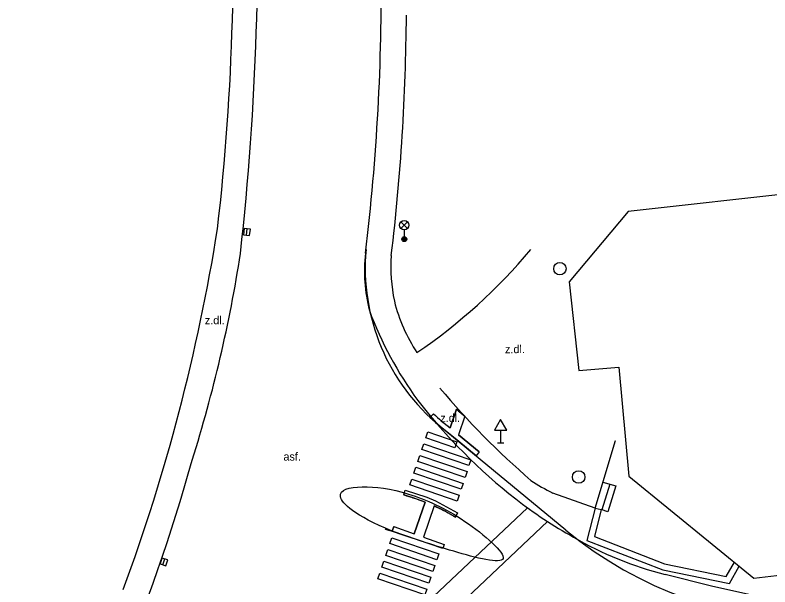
# Model space of a CAD drawing. Extents: x -438303 to -437792, y -1133191 to -1132731.
# Drawn here: x -438175.2 to -438114.5, y -1132946.7 to -1132900.7 of the extents above; entities that cross this region are included whole.
import ezdxf

# ---------------------------------------------------------------- set-up
doc = ezdxf.new("R2010")
doc.units = 0
for name, color, linetype in [('Vrstva 1', 7, 'Continuous'), ('Vrstva 10', 7, 'Continuous'), ('Vrstva 11', 7, 'Continuous'), ('Vrstva 15', 7, 'Continuous'), ('Vrstva 27', 7, 'Continuous'), ('Vrstva 33', 7, 'Continuous'), ('Vrstva 34', 7, 'Continuous'), ('Vrstva 40', 7, 'Continuous'), ('Vrstva 5', 7, 'Continuous'), ('Vrstva 7', 7, 'Continuous')]:
    doc.layers.add(name, color=color, linetype=linetype)

msp = doc.modelspace()

# ---------------------------------------------------------------- linework, layer by layer
at = {"layer": 'Vrstva 1'}
for p, q in [((-438155.826, -1132901.236), (-438155.826, -1132901.236)), ((-438146.119, -1132909.367), (-438146.119, -1132909.367)), ((-438144.089, -1132909.994), (-438144.089, -1132909.994)), ((-438158.968, -1132917.888), (-438158.968, -1132917.888)), ((-438156.605, -1132918.147), (-438156.605, -1132918.147)), ((-438143.948, -1132918.717), (-438143.948, -1132918.717)), ((-438133.773, -1132919.564), (-438133.773, -1132919.564)), ((-438157.123, -1132919.862), (-438157.123, -1132919.862)), ((-438147.077, -1132919.853), (-438147.077, -1132919.853)), ((-438144.992, -1132920.029), (-438144.992, -1132920.029)), ((-438131.436, -1132921.094), (-438131.436, -1132921.094)), ((-438130.703, -1132922.147), (-438130.703, -1132922.147)), ((-438144.742, -1132923.715), (-438144.742, -1132923.715)), ((-438137.844, -1132923.811), (-438137.844, -1132923.811)), ((-438146.756, -1132924.452), (-438146.756, -1132924.452)), ((-438142.928, -1132927.849), (-438142.928, -1132927.849)), ((-438129.904, -1132929.273), (-438129.904, -1132929.273)), ((-438126.696, -1132929.011), (-438126.696, -1132929.011)), ((-438144.325, -1132929.574), (-438144.325, -1132929.574)), ((-438141.088, -1132930.695), (-438141.088, -1132930.695)), ((-438142.868, -1132931.687), (-438142.868, -1132931.687)), ((-438130.954, -1132942.128), (-438141.052, -1132933.786)), ((-438130.954, -1132942.128), (-438141.052, -1132933.786)), ((-438126.959, -1132934.926), (-438126.959, -1132934.926)), ((-438139.65, -1132935.408), (-438139.65, -1132935.408)), ((-438136.952, -1132935.187), (-438136.952, -1132935.187)), ((-438136.203, -1132935.104), (-438136.203, -1132935.104)), ((-438161.005, -1132936.493), (-438161.005, -1132936.493)), ((-438129.924, -1132937.857), (-438129.924, -1132937.857)), ((-438125.902, -1132937.774), (-438125.902, -1132937.774)), ((-438133.761, -1132938.125), (-438133.761, -1132938.125)), ((-438132.011, -1132939.142), (-438132.011, -1132939.142)), ((-438126.949, -1132938.569), (-438126.949, -1132938.569)), ((-438134.991, -1132939.622), (-438134.991, -1132939.622)), ((-438128.609, -1132940.357), (-438128.609, -1132940.357)), ((-438130.345, -1132942.693), (-438130.345, -1132942.693)), ((-438129.257, -1132942.959), (-438129.257, -1132942.959)), ((-438127.039, -1132944.334), (-438127.039, -1132944.334)), ((-438163.277, -1132944.686), (-438163.277, -1132944.686)), ((-438123.158, -1132945.315), (-438123.158, -1132945.315)), ((-438122.981, -1132945.695), (-438122.981, -1132945.695)), ((-438117.804, -1132946.416), (-438117.804, -1132946.416)), ((-438115.841, -1132945.985), (-438115.841, -1132945.985)), ((-438119.248, -1132946.649), (-438119.248, -1132946.649))]:
    msp.add_line(p, q, dxfattribs=at)
for points in [[(-438139.738, -1132932.404), (-438139.086, -1132932.972), (-438139.597, -1132934.47), (-438137.94, -1132935.839), (-438138.158, -1132936.155), (-438139.718, -1132934.876), (-438141.052, -1132933.786), (-438141.891, -1132933.072), (-438141.61, -1132932.764), (-438140.978, -1132933.341), (-438140.25, -1132933.908)], [(-438139.738, -1132932.404), (-438139.086, -1132932.972), (-438139.597, -1132934.47), (-438137.94, -1132935.839), (-438138.158, -1132936.155), (-438139.718, -1132934.876), (-438141.052, -1132933.786), (-438141.891, -1132933.072), (-438141.61, -1132932.764), (-438140.978, -1132933.341), (-438140.25, -1132933.908)], [(-438142.21, -1132934.705), (-438142.049, -1132934.232), (-438139.718, -1132935.027), (-438139.879, -1132935.5)], [(-438142.21, -1132934.705), (-438142.049, -1132934.232), (-438139.718, -1132935.027), (-438139.879, -1132935.5)], [(-438142.533, -1132935.651), (-438142.372, -1132935.178), (-438138.589, -1132936.468), (-438138.751, -1132936.942)], [(-438142.533, -1132935.651), (-438142.372, -1132935.178), (-438138.589, -1132936.468), (-438138.751, -1132936.942)], [(-438142.856, -1132936.598), (-438142.695, -1132936.124), (-438138.902, -1132937.418), (-438139.063, -1132937.892)], [(-438142.856, -1132936.598), (-438142.695, -1132936.124), (-438138.902, -1132937.418), (-438139.063, -1132937.892)], [(-438143.179, -1132937.544), (-438143.018, -1132937.071), (-438139.215, -1132938.368), (-438139.377, -1132938.841)], [(-438143.179, -1132937.544), (-438143.018, -1132937.071), (-438139.215, -1132938.368), (-438139.377, -1132938.841)], [(-438143.502, -1132938.491), (-438143.341, -1132938.017), (-438139.536, -1132939.315), (-438139.698, -1132939.788)], [(-438143.502, -1132938.491), (-438143.341, -1132938.017), (-438139.536, -1132939.315), (-438139.698, -1132939.788)], [(-438145.113, -1132943.214), (-438144.952, -1132942.741), (-438141.167, -1132944.032), (-438141.328, -1132944.505)], [(-438145.113, -1132943.214), (-438144.952, -1132942.741), (-438141.167, -1132944.032), (-438141.328, -1132944.505)], [(-438145.436, -1132944.161), (-438145.275, -1132943.687), (-438141.491, -1132944.978), (-438141.652, -1132945.452)], [(-438145.436, -1132944.161), (-438145.275, -1132943.687), (-438141.491, -1132944.978), (-438141.652, -1132945.452)], [(-438145.759, -1132945.107), (-438145.598, -1132944.634), (-438141.815, -1132945.924), (-438141.977, -1132946.397)], [(-438145.759, -1132945.107), (-438145.598, -1132944.634), (-438141.815, -1132945.924), (-438141.977, -1132946.397)], [(-438146.082, -1132946.053), (-438145.921, -1132945.58), (-438142.135, -1132946.872), (-438142.297, -1132947.345)], [(-438146.082, -1132946.053), (-438145.921, -1132945.58), (-438142.135, -1132946.872), (-438142.297, -1132947.345)]]:
    msp.add_lwpolyline(points, close=True, dxfattribs=at)
for centre, radius, start, end in [((-438130.552, -1132921.006), 16.541, 174.90561, 230.59496), ((-438130.552, -1132921.006), 16.541, 174.90561, 230.59496), ((-438110.574, -1132917.458), 32, 230.44064, 309.22281), ((-438110.574, -1132917.458), 32, 230.44064, 309.22281)]:
    msp.add_arc(centre, radius, start, end, dxfattribs=at)
msp.add_open_spline([(-438144.925, -1132942.222), (-438147.969, -1132940.918), (-438149.969, -1132939.081), (-438147.599, -1132938.456), (-438143.711, -1132938.961), (-438139.154, -1132941.04), (-438134.17, -1132945.408), (-438140.182, -1132943.84), (-438144.925, -1132942.222), (-438146.493, -1132941.692), (-438142.547, -1132943.015)], degree=3, dxfattribs=at)
msp.add_open_spline([(-438144.925, -1132942.222), (-438147.969, -1132940.918), (-438149.969, -1132939.081), (-438147.599, -1132938.456), (-438143.711, -1132938.961), (-438139.154, -1132941.04), (-438134.17, -1132945.408), (-438140.182, -1132943.84), (-438144.925, -1132942.222), (-438146.493, -1132941.692), (-438142.547, -1132943.015)], degree=3, dxfattribs=at)
at = {"layer": 'Vrstva 10'}
for p, q in [((-438134.051, -1132940.322), (-438141.608, -1132947.471)), ((-438132.422, -1132941.437), (-438139.425, -1132948.062))]:
    msp.add_line(p, q, dxfattribs=at)
msp.add_lwpolyline([(-438095.883, -1132946.158), (-438105.153, -1132947.288), (-438110.001, -1132947.588), (-438116.012, -1132947.374), (-438119.248, -1132946.649), (-438122.981, -1132945.695)], dxfattribs=at)
for centre, radius, start, end in [((-438384.687, -1132894.657), 228.955, 353.67946, 2.60406), ((-438319.432, -1132898.821), 173.633, 353.04265, 0.68936), ((-438267.812, -1132902.796), 111.997, 342.48943, 351.2348), ((-438134.407, -1132921.278), 12.75, 173.58308, 194.41215), ((-438118.689, -1132914.03), 29.94, 200.3702, 216.13822), ((-438106.682, -1132903.648), 45.777, 217.77059, 231.80001), ((-438304.501, -1132896.34), 149.008, 330.16266, 344.36721), ((-438111.129, -1132908.563), 39.167, 232.46536, 240.61963), ((-438115.77, -1132917.481), 29.121, 239.96826, 255.66322)]:
    msp.add_arc(centre, radius, start, end, dxfattribs=at)
at = {"layer": 'Vrstva 11'}
for p, q in [((-438127.427, -1132938.423), (-438128.057, -1132940.498)), ((-438127.972, -1132938.258), (-438126.949, -1132938.569)), ((-438126.949, -1132938.569), (-438127.578, -1132940.643)), ((-438127.578, -1132940.643), (-438128.124, -1132940.478))]:
    msp.add_line(p, q, dxfattribs=at)
for points in [[(-438128.609, -1132940.357), (-438126.959, -1132934.926)], [(-438128.609, -1132940.357), (-438132.011, -1132939.142)]]:
    msp.add_lwpolyline(points, dxfattribs=at)
for centre, radius, start, end in [((-438353.363, -1132895.612), 195.668, 353.46313, 3.32406), ((-438315.666, -1132899.618), 171.89, 353.18022, 359.64229), ((-438312.123, -1132893.412), 155.099, 339.82033, 350.92032), ((-438168.757, -1132890.105), 45.735, 304.38545, 319.90079), ((-438132.462, -1132921.032), 12.57, 175.42625, 192.32563), ((-438132.137, -1132920.647), 12.973, 193.67954, 213.71924), ((-438092.463, -1132890.067), 63.365, 219.88012, 229.32653), ((-438125.543, -1132925.997), 14.65, 235.8789, 243.80027)]:
    msp.add_arc(centre, radius, start, end, dxfattribs=at)
at = {"layer": 'Vrstva 15'}
for p, q in [((-438139.738, -1132932.404), (-438140.25, -1132933.908)), ((-438139.738, -1132932.404), (-438140.25, -1132933.908)), ((-438141.61, -1132932.764), (-438141.891, -1132933.072)), ((-438141.61, -1132932.764), (-438141.891, -1132933.072)), ((-438139.086, -1132932.972), (-438139.597, -1132934.47)), ((-438139.086, -1132932.972), (-438139.597, -1132934.47)), ((-438137.94, -1132935.839), (-438139.597, -1132934.47)), ((-438137.94, -1132935.839), (-438139.597, -1132934.47)), ((-438137.94, -1132935.839), (-438138.158, -1132936.155)), ((-438137.94, -1132935.839), (-438138.158, -1132936.155)), ((-438143.997, -1132939.299), (-438143.865, -1132938.916)), ((-438143.997, -1132939.299), (-438143.865, -1132938.916)), ((-438142.283, -1132939.868), (-438143.154, -1132942.424)), ((-438142.283, -1132939.868), (-438143.154, -1132942.424)), ((-438141.544, -1132940.18), (-438142.4, -1132942.691)), ((-438141.544, -1132940.18), (-438142.4, -1132942.691)), ((-438139.832, -1132941.092), (-438139.665, -1132940.729)), ((-438139.832, -1132941.092), (-438139.665, -1132940.729)), ((-438144.796, -1132941.843), (-438144.925, -1132942.222)), ((-438144.796, -1132941.843), (-438144.925, -1132942.222)), ((-438144.796, -1132941.843), (-438143.154, -1132942.424)), ((-438144.796, -1132941.843), (-438143.154, -1132942.424)), ((-438142.4, -1132942.691), (-438140.75, -1132943.274)), ((-438142.4, -1132942.691), (-438140.75, -1132943.274)), ((-438140.75, -1132943.274), (-438140.855, -1132943.603)), ((-438140.75, -1132943.274), (-438140.855, -1132943.603))]:
    msp.add_line(p, q, dxfattribs=at)
msp.add_lwpolyline([(-438143.865, -1132938.916), (-438142.144, -1132939.483), (-438141.426, -1132939.764), (-438139.665, -1132940.729), (-438139.832, -1132941.092), (-438140.77, -1132940.555), (-438141.544, -1132940.18), (-438142.4, -1132942.691), (-438140.75, -1132943.274), (-438140.855, -1132943.603), (-438144.925, -1132942.222), (-438144.796, -1132941.843), (-438143.154, -1132942.424), (-438142.283, -1132939.868), (-438143.152, -1132939.557), (-438143.997, -1132939.299)], close=True, dxfattribs=at)
msp.add_lwpolyline([(-438143.865, -1132938.916), (-438142.144, -1132939.483), (-438141.426, -1132939.764), (-438139.665, -1132940.729), (-438139.832, -1132941.092), (-438140.77, -1132940.555), (-438141.544, -1132940.18), (-438142.4, -1132942.691), (-438140.75, -1132943.274), (-438140.855, -1132943.603), (-438144.925, -1132942.222), (-438144.796, -1132941.843), (-438143.154, -1132942.424), (-438142.283, -1132939.868), (-438143.152, -1132939.557), (-438143.997, -1132939.299)], close=True, dxfattribs=at)
for centre, start, end in [((-438128.81, -1132920.525), 227.39042, 230.45897), ((-438128.81, -1132920.525), 227.39042, 230.45897), ((-438130.552, -1132921.006), 226.75813, 233.06952), ((-438130.552, -1132921.006), 226.75813, 233.06952)]:
    msp.add_arc(centre, 16.141, start, end, dxfattribs=at)
for points, degree in [([(-438143.997, -1132939.299), (-438143.939, -1132939.315), (-438143.365, -1132939.484), (-438142.803, -1132939.666), (-438142.283, -1132939.868)], 3), ([(-438143.997, -1132939.299), (-438143.939, -1132939.315), (-438143.365, -1132939.484), (-438142.803, -1132939.666), (-438142.283, -1132939.868)], 3), ([(-438141.544, -1132940.18), (-438141.009, -1132940.423), (-438140.447, -1132940.718), (-438139.832, -1132941.092)], 2), ([(-438141.544, -1132940.18), (-438141.009, -1132940.423), (-438140.447, -1132940.718), (-438139.832, -1132941.092)], 2)]:
    msp.add_open_spline(points, degree=degree, dxfattribs=at)
at = {"layer": 'Vrstva 27'}
for p, q in [((-438156.635, -1132918.396), (-438156.576, -1132917.899)), ((-438163.354, -1132944.924), (-438163.201, -1132944.447))]:
    msp.add_line(p, q, dxfattribs=at)
for points in [[(-438156.386, -1132918.425), (-438156.328, -1132917.928), (-438156.825, -1132917.87), (-438156.883, -1132918.367)], [(-438163.115, -1132945), (-438162.962, -1132944.524), (-438163.439, -1132944.371), (-438163.592, -1132944.847)]]:
    msp.add_lwpolyline(points, close=True, dxfattribs=at)
for centre in [(-438131.436, -1132921.094), (-438129.924, -1132937.857)]:
    msp.add_circle(centre, 0.5, dxfattribs=at)
at = {"layer": 'Vrstva 33'}
for p, q in [((-438144.216, -1132917.328), (-438143.685, -1132917.857)), ((-438144.215, -1132917.858), (-438143.686, -1132917.327)), ((-438143.95, -1132917.967), (-438143.948, -1132918.717))]:
    msp.add_line(p, q, dxfattribs=at)
for centre, radius in [((-438143.95, -1132917.592), 0.375), ((-438143.948, -1132918.717), 0.2), ((-438143.948, -1132918.717), 0.145), ((-438143.948, -1132918.717), 0.0876)]:
    msp.add_circle(centre, radius, dxfattribs=at)
at = {"layer": 'Vrstva 34'}
for p, q in [((-438136.205, -1132934.086), (-438136.203, -1132935.104)), ((-438136.453, -1132935.105), (-438135.953, -1132935.104))]:
    msp.add_line(p, q, dxfattribs=at)
msp.add_lwpolyline([(-438136.705, -1132934.087), (-438135.705, -1132934.085), (-438136.207, -1132933.22)], close=True, dxfattribs=at)
at = {"layer": 'Vrstva 5'}
for p, q in [((-438130.703, -1132922.147), (-438129.904, -1132929.273)), ((-438129.904, -1132929.273), (-438126.696, -1132929.011)), ((-438126.696, -1132929.011), (-438125.902, -1132937.774)), ((-438125.902, -1132937.774), (-438115.841, -1132945.985)), ((-438115.841, -1132945.985), (-438103.741, -1132944.575))]:
    msp.add_line(p, q, dxfattribs=at)
msp.add_lwpolyline([(-438111.984, -1132914.94), (-438125.943, -1132916.489), (-438130.703, -1132922.147)], dxfattribs=at)
at = {"layer": 'Vrstva 7'}
for points in [[(-438128.609, -1132940.357), (-438129.257, -1132942.959), (-438123.158, -1132945.315), (-438117.804, -1132946.416), (-438117.009, -1132945.032)], [(-438128.609, -1132940.357), (-438128.124, -1132940.478)], [(-438128.124, -1132940.478), (-438128.666, -1132942.652), (-438123.017, -1132944.833), (-438118.058, -1132945.853), (-438117.402, -1132944.711)]]:
    msp.add_lwpolyline(points, dxfattribs=at)

# ---------------------------------------------------------------- texts
at = {"layer": 'Vrstva 40'}
for s, p in [('z.dl.', (-438159.987, -1132925.566)), ('z.dl.', (-438135.848, -1132927.892)), ('z.dl.', (-438141.052, -1132933.431)), ('asf.', (-438153.666, -1132936.537))]:
    msp.add_text(s, height=0.65, rotation=0.10417, dxfattribs=at).set_placement(p)

doc.saveas('drawing.dxf')
